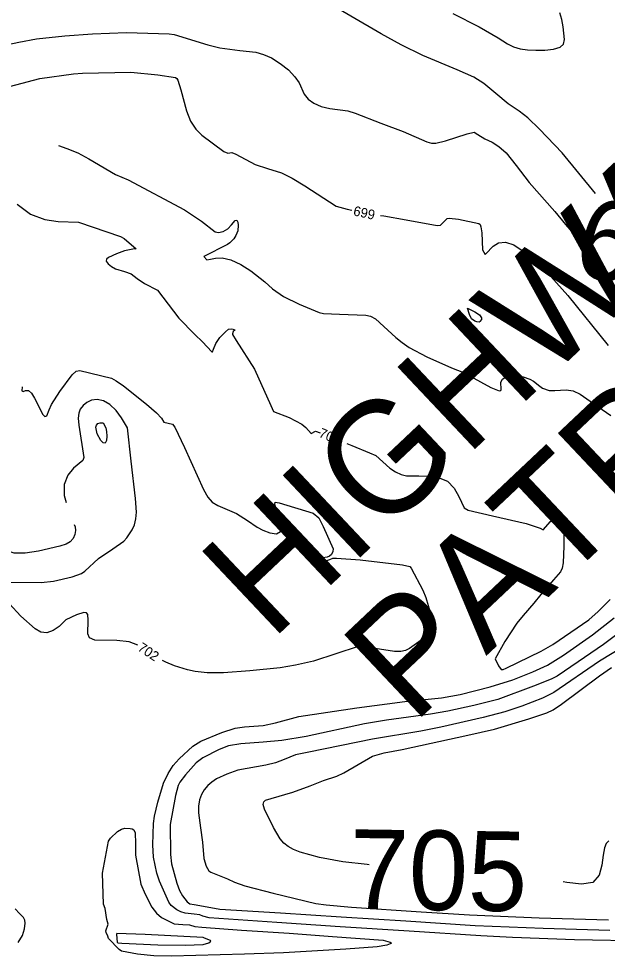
# Model space of a CAD drawing. Extents: x -291892836 to 2945206, y -477993085 to 1832792.
# Drawn here: x 1852255.7 to 1852499.7, y 543915.9 to 544304.4 of the extents above; entities that cross this region are included whole.
import ezdxf

# ---------------------------------------------------------------- set-up
doc = ezdxf.new("R2010")
doc.units = 0
for name, color, linetype in [('DT_X_Contour_Minor', 7, 'Continuous'), ('DT_X_Terrain_Ground_Line', 7, 'Continuous'), ('Level 19', 7, 'Continuous'), ('Level 40', 7, 'Continuous')]:
    doc.layers.add(name, color=color, linetype=linetype)

msp = doc.modelspace()

# ---------------------------------------------------------------- linework, layer by layer
at = {"layer": 'DT_X_Contour_Minor'}
for points in [[(1852494.85, 544231.97), (1852480.94, 544248.85), (1852471.62, 544258.72), (1852466.71, 544263.43), (1852463.16, 544266.17), (1852458.53, 544269.25), (1852453.53, 544273.49), (1852448.5, 544277.57), (1852444.3, 544280.17), (1852437.52, 544283.28), (1852423.27, 544289.28), (1852414.28, 544293.58), (1852405.9, 544298.18), (1852380.8, 544313.02)], [(1852435.65, 544306.69), (1852446.53, 544301.03), (1852454.4, 544296.51), (1852458.3, 544294.02), (1852460.81, 544292.84), (1852463.56, 544292.02), (1852466.6, 544291.57), (1852470.03, 544291.4), (1852473.83, 544291.46), (1852477.44, 544291.84), (1852480.19, 544292.64), (1852481.59, 544293.95), (1852481.95, 544295.79), (1852481.41, 544301.1), (1852480.89, 544304.15), (1852480.06, 544306.91)], [(1852244.59, 544292.35), (1852255.78, 544294.72), (1852263.11, 544296.12), (1852274.8, 544297.41), (1852286.3, 544298.26), (1852300.35, 544298.81), (1852318.04, 544298.21), (1852320.22, 544297.91), (1852334.16, 544293.62), (1852339.05, 544292.45), (1852347.34, 544291.33), (1852354.06, 544290.54), (1852357.23, 544289.68), (1852360.55, 544288.2), (1852364.12, 544285.96), (1852367.52, 544283.24), (1852370.23, 544280.43), (1852371.9, 544277.83), (1852374.08, 544273.25), (1852375.73, 544271.19), (1852378.05, 544269.4), (1852381.05, 544268.07), (1852384.66, 544267.29), (1852392.12, 544266.24), (1852395.2, 544265.36), (1852405.79, 544261.16), (1852415.04, 544257.75), (1852424.85, 544253.46), (1852426.88, 544252.95), (1852428.64, 544252.92), (1852432.66, 544253.83), (1852441.61, 544256.69), (1852444.51, 544257.44), (1852445.97, 544256.52), (1852448.92, 544254.65), (1852451.98, 544253.3), (1852454.76, 544251.52), (1852457.75, 544248.83), (1852461.89, 544243.62), (1852467.29, 544236.65), (1852477.93, 544224.61), (1852482.36, 544219.15), (1852491.57, 544208.53), (1852496.09, 544201.9), (1852504.64, 544189.17)], [(1852247, 544275.17), (1852264.52, 544279.62), (1852278.38, 544281.67), (1852282.11, 544281.94), (1852302.22, 544282.25), (1852313.4, 544281.14), (1852320.76, 544280.05), (1852321.29, 544279.64), (1852321.73, 544278.95), (1852322.96, 544274.96), (1852325.25, 544266.3), (1852326.98, 544261.94), (1852329.13, 544258.65), (1852331.59, 544256.22), (1852340.73, 544249.43), (1852342.33, 544248.69), (1852344.04, 544249.01), (1852345.69, 544248.38), (1852353.78, 544244.06), (1852358.79, 544242.35), (1852364.61, 544240.58), (1852369.07, 544238.37), (1852374.3, 544235.25), (1852387.27, 544226.75), (1852391.84, 544225.59), (1852393.86, 544225.14)], [(1852272.21, 544251.92), (1852275.71, 544250.74), (1852280.22, 544248.88), (1852284.83, 544246.39), (1852295.9, 544239.91), (1852301.03, 544237.67), (1852324.5, 544225.3), (1852331.53, 544220.56), (1852337.2, 544216.16), (1852338.47, 544215.87), (1852340.47, 544216.33), (1852342.39, 544217.45), (1852343.91, 544219.08), (1852345.47, 544220.78), (1852346.15, 544221.03), (1852346.55, 544220.19), (1852346.75, 544218.88), (1852346.48, 544216.53), (1852345.78, 544214.64), (1852344.92, 544213.3), (1852343.27, 544211.6), (1852342.23, 544210.93), (1852332.42, 544205.96), (1852333.74, 544204.54), (1852335.28, 544204.82), (1852337.23, 544205.24), (1852340.04, 544205.36), (1852343.61, 544204.61), (1852347.75, 544202.65), (1852351.88, 544200), (1852357.67, 544195.39), (1852360.86, 544192.48), (1852365.44, 544189.41), (1852372.01, 544186.13), (1852380.26, 544182.73), (1852382.06, 544182.31), (1852388.68, 544181.97), (1852399.6, 544181.63), (1852401.55, 544181.13), (1852403.54, 544180.06), (1852407.08, 544176.97), (1852411.99, 544172.35), (1852414.67, 544170.23), (1852417.6, 544168.27), (1852424.94, 544164.32), (1852435.1, 544159.78), (1852440.09, 544157.8), (1852451.35, 544151.61), (1852454.87, 544150.28), (1852455.53, 544150.4), (1852455.71, 544150.84), (1852455.54, 544153.79), (1852456.3, 544155.05), (1852457.57, 544156.04), (1852458.65, 544156.38), (1852460.24, 544156.53), (1852462.66, 544156.48), (1852464.76, 544156.11), (1852467.53, 544155.12), (1852469.14, 544154.23), (1852471.79, 544152.13), (1852472.77, 544151.42), (1852475.63, 544150.46), (1852477.99, 544150.38), (1852482.64, 544150.68), (1852485.52, 544150.2), (1852488.47, 544148.88), (1852494.03, 544145.02), (1852501.16, 544140.02)], [(1852255.02, 544227.62), (1852260.64, 544223.47), (1852266.59, 544221.2), (1852272.12, 544220.42), (1852280.48, 544220.15), (1852297.95, 544214.26), (1852299.46, 544213.41), (1852304.34, 544209.05), (1852302.99, 544208.92), (1852299.6, 544208.26), (1852296.2, 544206.98)], [(1852405.65, 544222.87), (1852407.09, 544222.71), (1852416.38, 544221.13), (1852429.17, 544218.79), (1852430.56, 544218.94), (1852432.96, 544221.31), (1852433.34, 544221.65), (1852434.1, 544221.81), (1852438.03, 544221.34), (1852446.43, 544219.66), (1852446.95, 544219.13), (1852447.33, 544218.22), (1852447.64, 544215.67), (1852447.94, 544208.62), (1852449.05, 544206.82), (1852449.34, 544206.99), (1852452.37, 544210.22), (1852454.6, 544211.55), (1852457.47, 544211.9), (1852460.94, 544210.69), (1852464.8, 544208.2), (1852468.79, 544204.9), (1852476.23, 544197.65), (1852483.35, 544189.7), (1852500.09, 544169.04)], [(1852296.2, 544206.98), (1852292.88, 544205.46), (1852292.12, 544204.83), (1852292, 544204.01), (1852292.73, 544202.93), (1852294.11, 544201.79), (1852295.87, 544200.8), (1852299.52, 544199.69), (1852302.27, 544198.76), (1852304.87, 544196.82), (1852307.89, 544194.71), (1852313.21, 544191.92), (1852322.12, 544180.37), (1852328.76, 544173.62), (1852331.91, 544170.59), (1852335.7, 544166.46), (1852336.08, 544166.48), (1852336.48, 544167.48), (1852337.44, 544169.82), (1852339.12, 544172.39), (1852341.39, 544174.73), (1852342.7, 544175.76), (1852343.99, 544175.95), (1852345.21, 544175.68), (1852345.34, 544175.46), (1852344.62, 544174.87), (1852344.31, 544173.91), (1852344.39, 544173.55), (1852345.9, 544171.08), (1852353.51, 544159.17), (1852360.25, 544144.18), (1852361.35, 544141.75), (1852367.88, 544139.15), (1852373.1, 544136.42), (1852374.74, 544135.03), (1852376.88, 544132.51), (1852378.72, 544133.5), (1852380.61, 544132.88)], [(1852444.79, 544179.07), (1852443.44, 544180.03), (1852442.62, 544181.85), (1852441.74, 544184.52), (1852444.82, 544183.04), (1852446.74, 544181.8), (1852447.48, 544180.5), (1852447.57, 544179.79), (1852446.86, 544178.94), (1852446.53, 544178.77), (1852445.62, 544178.83), (1852444.79, 544179.07)], [(1852257.08, 544151.91), (1852257.04, 544150.23), (1852257.52, 544150.04), (1852258.5, 544150.45), (1852259.74, 544150.44), (1852261.03, 544149.3), (1852262.31, 544147.24), (1852265.67, 544140.44), (1852266.58, 544139.56), (1852267.34, 544139.95), (1852268.4, 544142.45), (1852269.26, 544144.57), (1852272.76, 544149.95), (1852277.87, 544156.87), (1852279.59, 544158.43), (1852281.06, 544158.69), (1852294.13, 544155.44), (1852296.16, 544154.42), (1852299.13, 544152.34), (1852308.71, 544144.78), (1852312.81, 544141.18), (1852314.9, 544138.9), (1852315.92, 544137.21), (1852317.69, 544136.83), (1852319.47, 544136.46), (1852320.39, 544135.24), (1852324.44, 544126.77), (1852332.37, 544109.3), (1852334.12, 544106.16), (1852335.95, 544104.1), (1852338.2, 544102.72), (1852345.99, 544099.48), (1852350.56, 544096.57), (1852354.53, 544093.73), (1852356.91, 544092.45), (1852359.79, 544091.4), (1852362.52, 544091.03), (1852364.29, 544091.9), (1852364.54, 544094.28), (1852363.79, 544097.39), (1852361.92, 544103.21), (1852361.97, 544104.18), (1852363.64, 544103.83), (1852377.8, 544099.53), (1852380.12, 544097.61), (1852381.98, 544094.01), (1852386.05, 544084.79), (1852385.96, 544083.69), (1852385.3, 544082.38), (1852384.6, 544081.77), (1852383.57, 544081.31), (1852381.74, 544081.03), (1852378.47, 544081), (1852377.66, 544080.96), (1852381, 544080.17), (1852383.42, 544079.98), (1852384.68, 544080.29), (1852385.98, 544080.94), (1852387.44, 544080.97), (1852397.2, 544080.18), (1852414.84, 544078.17), (1852417.86, 544077.42), (1852418.44, 544076.74), (1852423.17, 544067.7), (1852424.5, 544064.55), (1852426.46, 544058.01), (1852427.36, 544053.18), (1852427.36, 544051.7), (1852427, 544050.59), (1852426.26, 544049.65), (1852423.57, 544047.61), (1852417.67, 544043.5), (1852416, 544042.64), (1852414.13, 544042.23), (1852411.44, 544042.3), (1852403.45, 544043.49), (1852397.89, 544044.43), (1852396.42, 544044.3), (1852377.84, 544038.26), (1852370.51, 544036.61), (1852364.1, 544035.52), (1852351.57, 544034.17), (1852340.61, 544033.4), (1852333.78, 544033.33), (1852328.81, 544033.98), (1852325.62, 544034.67), (1852320.25, 544036.34), (1852316.7, 544037.8), (1852315.29, 544038.56)], [(1852250.36, 544071.03), (1852265.07, 544070.8), (1852270.14, 544071.39), (1852277.92, 544073.2), (1852281.77, 544074.58), (1852283.07, 544075.52), (1852288.73, 544080.75), (1852294.69, 544084.77), (1852299.26, 544087.99), (1852300.58, 544089.34), (1852302.71, 544092.63), (1852303.66, 544094.77), (1852304.3, 544097.21), (1852304.51, 544099.92), (1852304.06, 544105.65), (1852302.28, 544121.06), (1852300.79, 544134.91), (1852298.27, 544139.13), (1852296.05, 544142.07), (1852293.5, 544144.6), (1852290.85, 544146.1), (1852288.29, 544146.6), (1852285.94, 544146.33), (1852283.95, 544145.48), (1852282.37, 544144.22), (1852281.24, 544142.72), (1852280.58, 544141.04), (1852280.38, 544138.92), (1852280.62, 544135.99), (1852282.73, 544122.63), (1852282.23, 544121.42), (1852278.49, 544118.15), (1852276.04, 544115.25), (1852274.5, 544111.46), (1852274.58, 544106.93), (1852275.33, 544104.04)], [(1852290.74, 544136.93), (1852291.8, 544134.89), (1852292.13, 544133.43), (1852292.26, 544131.53), (1852292.1, 544129.72), (1852291.61, 544128.63), (1852290.77, 544128.74), (1852289.78, 544129.73), (1852288.28, 544132.43), (1852287.71, 544135.21), (1852287.9, 544136.08), (1852288.52, 544136.72), (1852289.5, 544136.99), (1852290.74, 544136.93)], [(1852391.76, 544128.44), (1852393.79, 544127.58), (1852401.06, 544124.54), (1852403.72, 544123.39), (1852409.49, 544118.19), (1852411.86, 544116.73), (1852414.22, 544115.64), (1852416.39, 544115.09), (1852421.63, 544115), (1852425.45, 544114.96), (1852429.61, 544114.38), (1852433.39, 544112.79), (1852436.2, 544109.92), (1852438.11, 544106.52), (1852440.34, 544101.8), (1852442.08, 544100.79), (1852452.1, 544098.49), (1852466, 544095.33), (1852471.89, 544093.35), (1852473.1, 544092.6), (1852476.19, 544096.04), (1852477.48, 544097.04), (1852478.76, 544097.47), (1852479.89, 544097.05), (1852480.79, 544096), (1852481.39, 544094.67), (1852481.66, 544093.29), (1852481.66, 544085.83), (1852481.42, 544078.98), (1852481.03, 544076.8), (1852480.31, 544075.27), (1852477.41, 544071.93), (1852472.14, 544065.92), (1852469.22, 544062.28), (1852464.77, 544057.22), (1852462.17, 544053.91), (1852457.27, 544046.39), (1852453.18, 544039.25), (1852454.55, 544036.31), (1852455.75, 544034.81), (1852456.54, 544034.74), (1852457.76, 544035.27), (1852472.26, 544042.42), (1852477.07, 544045.16), (1852491.99, 544055.41), (1852495.88, 544058.77), (1852500.82, 544063.74)], [(1852278.69, 544094.83), (1852279.05, 544093.89), (1852279.24, 544092.39), (1852279, 544090.75), (1852278.3, 544089.09), (1852277.1, 544087.67), (1852275.33, 544086.66), (1852272.7, 544085.85), (1852263.85, 544083.87), (1852258.43, 544083.01), (1852253.78, 544082.97), (1852252.64, 544083.35)], [(1852305.07, 544044.87), (1852301.54, 544046.22), (1852296.4, 544046.75), (1852287.22, 544046.92), (1852285.06, 544047.93), (1852284.33, 544049.52), (1852284.5, 544055.18), (1852284.35, 544057.61), (1852283.78, 544058.31), (1852282.69, 544058.38), (1852279.71, 544057.37), (1852275.23, 544055.31), (1852272.42, 544052.65), (1852270.04, 544050.9), (1852267.43, 544049.92), (1852264.9, 544050.31), (1852262.55, 544051.69), (1852256.57, 544056.83), (1852251.79, 544062.06)], [(1852516.04, 543922.17), (1852486.03, 543922.73), (1852460.33, 543923.7), (1852447.27, 543924.35), (1852417.51, 543926.4), (1852388.99, 543928.16), (1852362.65, 543929.97), (1852334.71, 543931.8), (1852332.07, 543932.49), (1852330.81, 543933.04), (1852328.43, 543933.38), (1852324.77, 543933.78), (1852322.88, 543934.3), (1852321.24, 543935.15), (1852318.95, 543937.03), (1852317.88, 543938.42), (1852314.14, 543947.06), (1852313.01, 543950.34), (1852311.63, 543957.06), (1852311.31, 543962.17), (1852311.61, 543970.93), (1852312.02, 543974.04), (1852313.42, 543979.73), (1852315.72, 543987.71), (1852317.65, 543991.73), (1852319.72, 543994.99), (1852322.18, 543997.72), (1852327.93, 544002.99), (1852331.24, 544005.08), (1852339.94, 544008.71), (1852345.41, 544010.5), (1852349.25, 544010.96), (1852357.05, 544011.62), (1852362.21, 544012.73), (1852371.76, 544015.34), (1852395.81, 544018.89), (1852415.82, 544021.51), (1852430.99, 544023.03), (1852438.76, 544024.43), (1852451.11, 544027.56), (1852460.55, 544030.55), (1852468.82, 544033.75), (1852474.87, 544036.6), (1852481.49, 544040.72), (1852493.6, 544049.12), (1852502.54, 544056.16)], [(1852503.69, 544049.31), (1852498.1, 544045.2), (1852487.64, 544037.98), (1852478.89, 544031.96), (1852476.42, 544030.73), (1852469.07, 544027.82), (1852454.32, 544022.4), (1852444.38, 544019.91), (1852433.59, 544017.44), (1852426.39, 544016.25), (1852408.22, 544013.78), (1852398.99, 544012.25), (1852374.91, 544006.95), (1852364.82, 544005.3), (1852357.03, 544004.61), (1852347.8, 544003.93), (1852342.66, 544003.08), (1852338.84, 544001.59), (1852332.01, 543998.12), (1852329.26, 543996.1), (1852324.84, 543991.19), (1852322.44, 543988.08), (1852321.79, 543986.74), (1852320.74, 543982.54), (1852318.56, 543970.48), (1852318.68, 543958.06), (1852319.11, 543954.19), (1852321.23, 543946.25), (1852322.37, 543943.18), (1852323.64, 543940.94), (1852325.57, 543938.51), (1852326.71, 543937.72), (1852328.38, 543937.39), (1852333.88, 543936.46), (1852339.1, 543935.42), (1852364.26, 543933.97), (1852389.31, 543932.32), (1852416.14, 543930.62), (1852444.9, 543928.71), (1852473.07, 543927.53), (1852500.77, 543926.74)], [(1852507, 544044.56), (1852496.47, 544038.18), (1852477.54, 544025.2), (1852472.88, 544022.9), (1852464.23, 544019.55), (1852457.23, 544017.29), (1852448.21, 544014.89), (1852430.72, 544010.83), (1852422.33, 544009.18), (1852402.37, 544005.86), (1852376.01, 544000.53), (1852370.47, 543999.35), (1852365.74, 543997.54), (1852362.09, 543996.03), (1852358.19, 543995.1), (1852346.61, 543993), (1852341.95, 543991.44), (1852337.72, 543989.41), (1852335.79, 543988.15), (1852334.06, 543986.68), (1852332.58, 543984.96), (1852331.43, 543982.98), (1852330.64, 543980.72), (1852330.25, 543978.16), (1852330.25, 543975.34), (1852331.13, 543969.13), (1852331.88, 543963.26), (1852332.49, 543956.4), (1852333.38, 543953.23), (1852334.5, 543951.33), (1852335.39, 543950.74), (1852342.3, 543948), (1852345.21, 543946.67), (1852349.38, 543945.15), (1852361.13, 543942.04), (1852378.81, 543937.87), (1852383.09, 543937.21), (1852393.66, 543936.23), (1852422.49, 543934.32), (1852442.52, 543933.08), (1852471.49, 543931.91), (1852500.22, 543931.09)], [(1852400.96, 543953.88), (1852400.22, 543953.91), (1852390, 543955.07), (1852380.38, 543956.85), (1852372.35, 543959.14), (1852369.61, 543960.19), (1852367.39, 543961.39), (1852365.59, 543962.82), (1852364.06, 543964.59), (1852361.3, 543969.26), (1852357.59, 543976.95), (1852357.07, 543978.83), (1852357.28, 543980), (1852357.95, 543980.62), (1852360.33, 543981.33), (1852369.36, 543984.01), (1852376.56, 543986.63), (1852382, 543988.82), (1852387.55, 543990.61), (1852390.5, 543991.9), (1852402.43, 543998.91), (1852407.26, 544000.2), (1852414.62, 544001.66), (1852441.81, 544007.57), (1852452.99, 544010.08), (1852467.12, 544014.33), (1852474.59, 544016.81), (1852477.21, 544018.11), (1852480.69, 544020.41), (1852496.46, 544032.1), (1852501.44, 544035.6)], [(1852385.75, 543924.18), (1852406.83, 543922.56), (1852409.73, 543921.73), (1852410.23, 543921.38), (1852409.72, 543921.03), (1852408.33, 543920.54), (1852404.29, 543919.86), (1852391.26, 543918.84), (1852365.43, 543917.41), (1852349.29, 543916.74), (1852319.11, 543915.95), (1852311.69, 543916.13), (1852304.96, 543916.83), (1852298.31, 543918.04), (1852297.29, 543918.73), (1852292.89, 543923.27), (1852292.63, 543924.31), (1852291.94, 543925.73), (1852291.85, 543926.51), (1852292.81, 543929.26), (1852292.24, 543931.17), (1852291.6, 543935.67), (1852290.85, 543937.46), (1852290.48, 543950.31), (1852292.94, 543963.63), (1852293.72, 543964.83), (1852296.64, 543967.62), (1852298.29, 543968.65), (1852299.72, 543969.09), (1852301.94, 543968.93), (1852302.8, 543968.75), (1852303.48, 543968.28), (1852303.93, 543967.12), (1852304.13, 543962.63), (1852304.13, 543957.8), (1852306.37, 543945.85), (1852308.1, 543941.61), (1852310.84, 543936.23), (1852312.81, 543933.75), (1852314.94, 543932.03), (1852320.12, 543929.4), (1852323.81, 543929.13), (1852326.49, 543928.91), (1852328.75, 543928.33), (1852331.58, 543927.94), (1852348.03, 543926.79), (1852367.77, 543925.49), (1852385.75, 543924.18)], [(1852500.33, 543963.75), (1852499.28, 543962.69), (1852498.47, 543960.83), (1852497.91, 543957.85), (1852497.46, 543953.71), (1852496.36, 543949.49), (1852493.7, 543946.53), (1852488.94, 543945.78), (1852482.95, 543946.53), (1852481.42, 543946.83)], [(1852255.52, 543921.59), (1852257.27, 543924.48), (1852258.13, 543927.34), (1852258.38, 543929.61), (1852258.19, 543930.85), (1852257.71, 543931.98), (1852255.99, 543933.73), (1852254.27, 543935.61)], [(1852332.22, 543923.68), (1852308.18, 543925.02), (1852296.39, 543925.33), (1852296.19, 543924.91), (1852296.49, 543921.72), (1852296.77, 543921.57), (1852298.44, 543921.43), (1852313.4, 543920.72), (1852324.72, 543920.48), (1852332.22, 543920.86), (1852334.54, 543921.53), (1852335.42, 543922.15), (1852335.17, 543922.47), (1852332.78, 543923.47), (1852332.22, 543923.68)]]:
    msp.add_lwpolyline(points, dxfattribs=at)

# ---------------------------------------------------------------- texts
at = {"layer": 'DT_X_Terrain_Ground_Line'}
for s, rotation, p in [('695', 345.9462, (1852484.14, 544199.47)), ('705', 359.1872, (1852392.66, 543935.58))]:
    msp.add_text(s, height=33, rotation=rotation, dxfattribs=at).set_placement(p)
at = {"layer": 'Level 19'}
for s, rotation, p in [('699', 347.5046, (1852394.15, 544223.03)), ('701', 337.1971, (1852379.79, 544131.3)), ('702', 326.3052, (1852304.71, 544042.93))]:
    msp.add_text(s, height=4, rotation=rotation, dxfattribs=at).set_placement(p)
at = {"layer": 'Level 40'}
for s, p in [('HIGHWAY', (1852360.21, 544046.22)), ('PATROL', (1852419.06, 544011.63))]:
    msp.add_text(s, height=46.8, rotation=43.3446, dxfattribs=at).set_placement(p)

doc.saveas('drawing.dxf')
